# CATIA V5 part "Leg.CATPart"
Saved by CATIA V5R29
Part number: Leg
Source: Unknown
Bounding box of the stored display mesh (mm): x -40 to 40, y -50 to 50, z 0 to 600
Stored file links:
  C:\가치같이\SmartFactory_BoxErectorConveyor\Boxing(over)\Leg.CATPart
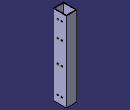
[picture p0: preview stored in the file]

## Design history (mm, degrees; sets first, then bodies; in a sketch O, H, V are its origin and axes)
Body1 (main body)
  Solid1 "PartBody": solid without history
